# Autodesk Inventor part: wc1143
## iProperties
Shininess: 64.0
Length Units: 11272
Angle Units: 11279
Time Units: 11290
Mass Units: 11286
Length Display Precision: 3
Angle Display Precision: 2
Compacted: True
Part Number: wc1143
Document SubType Name: Modeling
Created: 2004-08
Designer: John Blackburn
Manufacturer: Standard
Standards Organization: Custom
Material: Lexan, Clear
Density: 0.0
Volumn: 0.0
Area: 0.0
PropertySet Name: Model Information
Control State: 0
Master: False
Checked Out: False
Author: John Blackburn
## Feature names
1. Base1
